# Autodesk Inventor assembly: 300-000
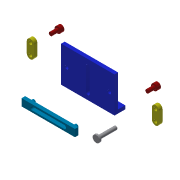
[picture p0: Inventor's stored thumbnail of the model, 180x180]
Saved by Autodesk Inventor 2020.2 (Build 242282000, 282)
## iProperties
Created: 2014-01
Part Number: 300-000
Document SubType Name: Assembly
Designer: F.Stasiak
Manager: www.cadconsulting.pl
Company: Fabian Stasiak CAD Consulting
Author: F.Stasiak
Subject: Zbiór ćwiczeń. Autodesk Inventor 2020. Kurs podstawowy
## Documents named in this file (6)
- C:\2020_Kurs_podstawowy\R6 Zespoły\Warsztat\300-000.iam
- C:\2020_Kurs_podstawowy\R6 Zespoły\Warsztat\Komponenty\300-001.ipt
- C:\2020_Kurs_podstawowy\R6 Zespoły\Warsztat\Komponenty\300-002.ipt
- C:\2020_Kurs_podstawowy\R6 Zespoły\Warsztat\Komponenty\300-003.ipt
- C:\2020_Kurs_podstawowy\R6 Zespoły\Warsztat\Komponenty\300-004.ipt
- C:\2020_Kurs_podstawowy\R6 Zespoły\Warsztat\Komponenty\300-005.ipt
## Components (7 placed, 5 different names)
1. 300-001:1
2. 300-002:1
3. 300-002:2
4. 300-003:1
5. 300-004:1
6. 300-004:2
7. 300-005:1
